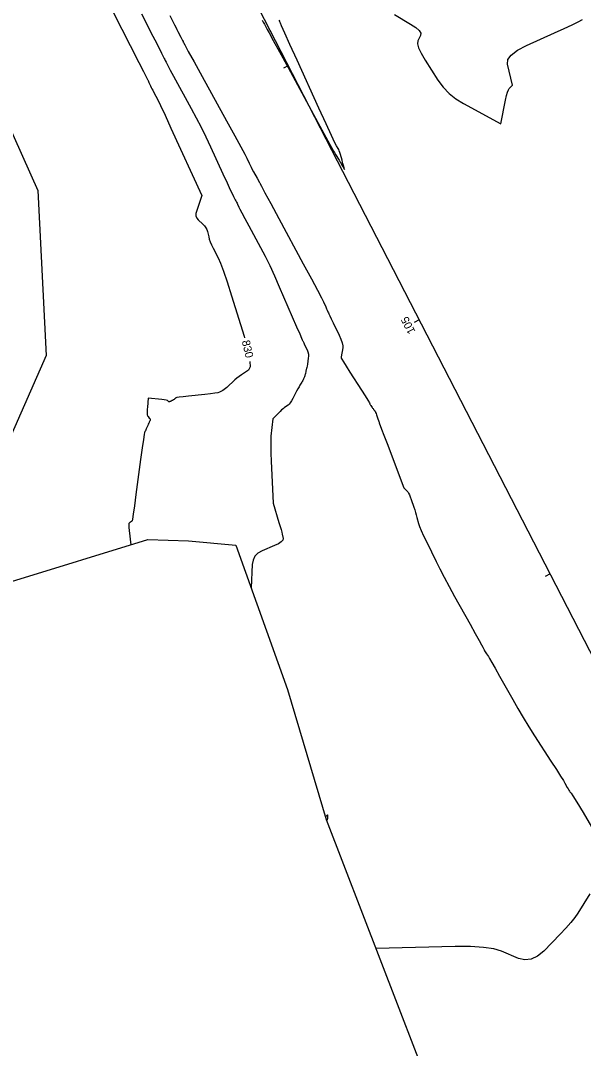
# Model space of a CAD drawing. Extents: x 1715724 to 1716561, y 394063 to 395906.
# Drawn here: x 1716070.7 to 1716169.2, y 394769.7 to 394949.5 of the extents above; entities that cross this region are included whole.
import ezdxf

# ---------------------------------------------------------------- set-up
doc = ezdxf.new("R2010")
doc.units = 0
for name, color, linetype in [('DT_X_Contour_Major', 7, 'Continuous'), ('DT_X_Contour_Minor', 7, 'Continuous'), ('DT_X_TIN_Hull', 7, 'Continuous'), ('GE_P_CL_10', 7, 'Continuous')]:
    doc.layers.add(name, color=color, linetype=linetype)

msp = doc.modelspace()

# ---------------------------------------------------------------- linework, layer by layer
at = {"layer": 'DT_X_Contour_Major'}
for points in [[(1716086.92, 394951.04), (1716091.41, 394942.22), (1716092.21, 394940.65), (1716092.69, 394939.69), (1716092.87, 394939.34), (1716092.92, 394939.24), (1716092.95, 394939.18), (1716093, 394939.07), (1716093.08, 394938.91), (1716093.17, 394938.71), (1716093.46, 394938.1), (1716093.57, 394937.86), (1716093.69, 394937.62), (1716093.83, 394937.36), (1716093.98, 394937.09), (1716094.39, 394936.34), (1716094.66, 394935.78), (1716095.19, 394934.66), (1716095.98, 394932.98), (1716097.01, 394930.73), (1716102.41, 394918.93), (1716101.52, 394916.34), (1716101.39, 394915.82), (1716101.39, 394915.37), (1716101.51, 394914.98), (1716101.76, 394914.66), (1716102.6, 394913.91), (1716102.88, 394913.61), (1716103.11, 394913.3), (1716103.28, 394912.98), (1716103.39, 394912.64), (1716103.61, 394911.7), (1716103.72, 394911.31), (1716103.89, 394910.85), (1716104.12, 394910.32), (1716104.42, 394909.72), (1716105.28, 394908.02), (1716105.67, 394907.13), (1716106.18, 394905.73), (1716106.82, 394903.83), (1716107.59, 394901.42), (1716109.8, 394894.32), (1716109.89, 394894.02)], [(1716110.82, 394889.93), (1716110.85, 394888.99), (1716110.56, 394888.4), (1716109.35, 394887.59), (1716108.92, 394887.29), (1716108.53, 394887), (1716108.18, 394886.7), (1716107.87, 394886.42), (1716107.09, 394885.65), (1716106.81, 394885.38), (1716106.54, 394885.16), (1716106.3, 394884.98), (1716106.08, 394884.85), (1716105.53, 394884.56), (1716105.21, 394884.45), (1716104.68, 394884.34), (1716103.92, 394884.23), (1716102.96, 394884.12), (1716100.09, 394883.83), (1716099.15, 394883.73), (1716098.47, 394883.66), (1716098.05, 394883.6), (1716097.9, 394883.57), (1716097.85, 394883.52), (1716097.84, 394883.5), (1716097.81, 394883.48), (1716097.79, 394883.46), (1716097.77, 394883.44), (1716097.7, 394883.38), (1716097.67, 394883.35), (1716097.64, 394883.33), (1716097.6, 394883.3), (1716097.57, 394883.28), (1716097.46, 394883.2), (1716097.41, 394883.18), (1716097.36, 394883.14), (1716097.29, 394883.11), (1716097.22, 394883.07), (1716097.02, 394882.97), (1716096.95, 394882.93), (1716096.89, 394882.9), (1716096.84, 394882.88), (1716096.8, 394882.86), (1716096.72, 394882.83), (1716096.69, 394882.82), (1716096.66, 394882.83), (1716096.62, 394882.86), (1716096.58, 394882.9), (1716096.48, 394883.02), (1716096.38, 394883.07), (1716096.17, 394883.12), (1716095.84, 394883.18), (1716095.39, 394883.23), (1716093.02, 394883.51), (1716092.89, 394881.89), (1716092.86, 394881.57), (1716092.85, 394881.31), (1716092.84, 394881.12), (1716092.83, 394880.98), (1716092.83, 394880.7), (1716092.85, 394880.59), (1716092.88, 394880.48), (1716092.93, 394880.38), (1716093, 394880.28), (1716093.22, 394880.01), (1716093.3, 394879.91), (1716093.35, 394879.84), (1716093.38, 394879.79), (1716093.38, 394879.75), (1716093.37, 394879.69), (1716093.37, 394879.65), (1716093.35, 394879.61), (1716093.33, 394879.56), (1716093.31, 394879.5), (1716093.22, 394879.31), (1716093.18, 394879.23), (1716093.13, 394879.1), (1716093.05, 394878.93), (1716092.96, 394878.73), (1716092.69, 394878.13), (1716092.6, 394877.93), (1716092.53, 394877.77), (1716092.47, 394877.66), (1716092.44, 394877.59), (1716092.37, 394877.47), (1716092.31, 394877.14), (1716092.18, 394876.25), (1716091.98, 394874.79), (1716091.71, 394872.78), (1716090.89, 394866.65), (1716090.62, 394864.64), (1716090.41, 394863.19), (1716090.28, 394862.32), (1716090.22, 394862.01), (1716090.14, 394861.95), (1716090.11, 394861.93), (1716090.09, 394861.92), (1716090.08, 394861.91), (1716090.08, 394861.9), (1716090.07, 394861.9), (1716090.06, 394861.9), (1716090.05, 394861.89), (1716090.03, 394861.87), (1716090, 394861.86), (1716089.92, 394861.8), (1716089.89, 394861.78), (1716089.86, 394861.75), (1716089.82, 394861.71), (1716089.78, 394861.66), (1716089.67, 394861.54), (1716089.64, 394861.43), (1716089.64, 394861.2), (1716089.66, 394860.84), (1716089.71, 394860.36), (1716089.99, 394857.84)]]:
    msp.add_lwpolyline(points, dxfattribs=at)
at = {"layer": 'DT_X_Contour_Minor'}
for points in [[(1716091.87, 394950.73), (1716093.86, 394946.82), (1716094.52, 394945.51), (1716095.37, 394943.84), (1716095.56, 394943.48), (1716095.83, 394942.93), (1716095.93, 394942.73), (1716096.02, 394942.55), (1716096.17, 394942.25), (1716096.34, 394941.89), (1716096.5, 394941.57), (1716096.87, 394940.89), (1716097.44, 394939.84), (1716100.57, 394934.17), (1716101.44, 394932.55), (1716102.29, 394930.89), (1716103.13, 394929.18), (1716103.95, 394927.43), (1716106.11, 394922.71), (1716106.84, 394921.13), (1716107.39, 394919.94), (1716107.76, 394919.15), (1716107.97, 394918.75), (1716108.27, 394918.2), (1716108.38, 394918), (1716108.49, 394917.8), (1716108.58, 394917.6), (1716108.67, 394917.41), (1716108.89, 394916.9), (1716109.07, 394916.55), (1716109.41, 394915.9), (1716109.93, 394914.93), (1716110.62, 394913.65), (1716112.69, 394909.82), (1716113.47, 394908.32), (1716114.28, 394906.68), (1716115.1, 394904.9), (1716115.95, 394902.99), (1716118.24, 394897.71), (1716118.99, 394895.98), (1716119.53, 394894.73), (1716119.86, 394893.97), (1716119.99, 394893.69), (1716120.03, 394893.6), (1716120.07, 394893.53), (1716120.14, 394893.38), (1716120.25, 394893.15), (1716120.4, 394892.84), (1716120.84, 394891.92), (1716120.97, 394891.57), (1716121.05, 394891.21), (1716121.07, 394890.84), (1716121.04, 394890.46), (1716120.87, 394889.44), (1716120.82, 394889.1), (1716120.77, 394888.85), (1716120.74, 394888.68), (1716120.72, 394888.61), (1716120.68, 394888.51), (1716120.66, 394888.46), (1716120.64, 394888.39), (1716120.62, 394888.29), (1716120.59, 394888.16), (1716120.52, 394887.79), (1716120.49, 394887.65), (1716120.45, 394887.51), (1716120.41, 394887.37), (1716120.35, 394887.23), (1716120.2, 394886.85), (1716120.14, 394886.71), (1716120.07, 394886.57), (1716119.99, 394886.43), (1716119.91, 394886.3), (1716119.67, 394885.94), (1716119.57, 394885.76), (1716119.42, 394885.5), (1716119.23, 394885.15), (1716119, 394884.72), (1716118.35, 394883.45), (1716118.11, 394883.02), (1716117.89, 394882.68), (1716117.68, 394882.43), (1716117.5, 394882.27), (1716117.02, 394881.95), (1716116.83, 394881.81), (1716116.62, 394881.63), (1716116.37, 394881.42), (1716116.11, 394881.16), (1716114.81, 394879.88), (1716114.51, 394876.87), (1716114.47, 394876.11), (1716114.46, 394875.12), (1716114.48, 394873.89), (1716114.54, 394872.44), (1716114.89, 394865.12), (1716115.91, 394861.72), (1716116.11, 394861.05), (1716116.27, 394860.49), (1716116.39, 394860.04), (1716116.47, 394859.7), (1716116.63, 394858.94), (1716116.58, 394858.64), (1716116.31, 394858.34), (1716115.82, 394858.02), (1716115.12, 394857.69), (1716112.95, 394856.78), (1716112.23, 394856.38), (1716111.71, 394855.84), (1716111.38, 394855.17), (1716111.24, 394854.37), (1716111.03, 394850.32)], [(1716096.82, 394950.42), (1716097.42, 394949.24), (1716097.64, 394948.81), (1716097.85, 394948.39), (1716098.05, 394948), (1716098.24, 394947.62), (1716098.75, 394946.62), (1716098.92, 394946.29), (1716099.04, 394946.04), (1716099.12, 394945.88), (1716099.17, 394945.79), (1716099.22, 394945.68), (1716099.43, 394945.28), (1716100.05, 394944.16), (1716101.06, 394942.33), (1716102.47, 394939.77), (1716106.75, 394932), (1716108.17, 394929.41), (1716109.23, 394927.46), (1716109.93, 394926.15), (1716110.27, 394925.49), (1716110.68, 394924.59), (1716110.84, 394924.25), (1716111.03, 394923.88), (1716111.23, 394923.49), (1716111.46, 394923.08), (1716112.09, 394921.95), (1716112.3, 394921.58), (1716112.45, 394921.3), (1716112.55, 394921.13), (1716112.59, 394921.04), (1716112.63, 394920.96), (1716112.84, 394920.56), (1716113.45, 394919.42), (1716114.46, 394917.55), (1716115.87, 394914.94), (1716120.16, 394907.01), (1716121.58, 394904.37), (1716122.65, 394902.38), (1716123.34, 394901.05), (1716123.68, 394900.37), (1716124.08, 394899.45), (1716124.21, 394899.13), (1716124.32, 394898.89), (1716124.4, 394898.71), (1716124.46, 394898.61), (1716124.56, 394898.41), (1716124.64, 394898.24), (1716124.81, 394897.9), (1716125.06, 394897.37), (1716125.4, 394896.66), (1716126.41, 394894.53), (1716126.74, 394893.79), (1716126.96, 394893.16), (1716127.06, 394892.66), (1716127.06, 394892.27), (1716126.81, 394890.72), (1716126.8, 394890.51), (1716126.9, 394890.32), (1716127.18, 394889.85), (1716127.65, 394889.1), (1716128.31, 394888.06), (1716130.33, 394884.9), (1716130.99, 394883.87), (1716131.46, 394883.12), (1716131.74, 394882.66), (1716131.83, 394882.5), (1716131.81, 394882.45), (1716131.81, 394882.42), (1716131.84, 394882.36), (1716131.89, 394882.28), (1716131.97, 394882.18), (1716132.21, 394881.87), (1716132.29, 394881.76), (1716132.36, 394881.67), (1716132.42, 394881.59), (1716132.47, 394881.53), (1716132.57, 394881.38), (1716132.61, 394881.33), (1716132.64, 394881.29), (1716132.67, 394881.25), (1716132.69, 394881.22), (1716132.74, 394881.15), (1716132.77, 394881.09), (1716132.81, 394880.97), (1716132.88, 394880.8), (1716132.96, 394880.56), (1716133.21, 394879.85), (1716133.29, 394879.61), (1716133.36, 394879.42), (1716133.41, 394879.27), (1716133.45, 394879.18), (1716133.52, 394879), (1716133.62, 394878.73), (1716133.87, 394878.07), (1716134.27, 394877), (1716134.82, 394875.55), (1716137.72, 394867.82), (1716138.42, 394867.08), (1716138.57, 394866.87), (1716138.72, 394866.59), (1716138.88, 394866.22), (1716139.05, 394865.76), (1716139.5, 394864.44), (1716139.65, 394863.96), (1716139.8, 394863.49), (1716139.93, 394863.06), (1716140.04, 394862.64), (1716140.33, 394861.57), (1716140.5, 394861.06), (1716140.79, 394860.34), (1716141.21, 394859.41), (1716141.76, 394858.27), (1716143.38, 394854.93), (1716144.05, 394853.61), (1716144.81, 394852.15), (1716145.67, 394850.54), (1716146.64, 394848.79), (1716149.35, 394843.93), (1716150.25, 394842.31), (1716150.92, 394841.1), (1716151.35, 394840.31), (1716151.56, 394839.93), (1716151.79, 394839.46), (1716151.88, 394839.28), (1716151.98, 394839.11), (1716152.09, 394838.93), (1716152.21, 394838.75), (1716152.54, 394838.28), (1716152.76, 394837.94), (1716153.16, 394837.25), (1716153.74, 394836.23), (1716154.5, 394834.86), (1716156.79, 394830.76), (1716157.67, 394829.21), (1716158.6, 394827.63), (1716159.59, 394826.02), (1716160.63, 394824.39), (1716163.48, 394819.99), (1716164.44, 394818.51), (1716165.16, 394817.37), (1716165.66, 394816.58), (1716165.93, 394816.13), (1716166.34, 394815.39), (1716166.48, 394815.14), (1716166.61, 394814.93), (1716166.72, 394814.76), (1716166.81, 394814.64), (1716167.04, 394814.39), (1716167.32, 394813.95), (1716168.01, 394812.81), (1716169.1, 394810.99), (1716170.6, 394808.47)], [(1716112.97, 394949.64), (1716113.17, 394949.27), (1716113.35, 394948.94), (1716113.5, 394948.66), (1716113.87, 394947.99), (1716114.2, 394947.38), (1716114.91, 394946.07), (1716116.01, 394944.05), (1716117.49, 394941.32), (1716121.95, 394933.11), (1716123.42, 394930.42), (1716124.47, 394928.49), (1716125.1, 394927.33), (1716125.31, 394926.94), (1716125.33, 394926.91), (1716125.36, 394926.85), (1716125.45, 394926.7), (1716125.6, 394926.46), (1716125.8, 394926.12), (1716126.41, 394925.1), (1716126.61, 394924.77), (1716126.76, 394924.52), (1716126.85, 394924.36), (1716126.89, 394924.3), (1716126.92, 394924.25), (1716126.94, 394924.22), (1716126.97, 394924.16), (1716127.01, 394924.09), (1716127.07, 394924), (1716127.36, 394923.51), (1716127.23, 394924.06), (1716127.2, 394924.17), (1716127.18, 394924.24), (1716127.17, 394924.29), (1716127.16, 394924.31), (1716127.15, 394924.33), (1716127.13, 394924.39), (1716127.09, 394924.53), (1716127.03, 394924.77), (1716126.94, 394925.1), (1716126.67, 394926.1), (1716126.56, 394926.45), (1716126.46, 394926.74), (1716126.36, 394926.99), (1716126.25, 394927.18), (1716125.97, 394927.63), (1716125.7, 394928.17), (1716125.1, 394929.46), (1716124.16, 394931.48), (1716122.9, 394934.25), (1716119.08, 394942.61), (1716117.82, 394945.37), (1716116.92, 394947.37), (1716116.36, 394948.6), (1716116.16, 394949.07), (1716116.08, 394949.3), (1716116.03, 394949.43), (1716115.94, 394949.64)], [(1716136.14, 394950.59), (1716138.94, 394948.9), (1716139.84, 394948.31), (1716140.43, 394947.78), (1716140.7, 394947.32), (1716140.67, 394946.93), (1716140.17, 394945.98), (1716140.12, 394945.5), (1716140.31, 394944.79), (1716140.76, 394943.83), (1716141.47, 394942.64), (1716143.7, 394939.14), (1716144.6, 394937.89), (1716145.65, 394936.79), (1716146.84, 394935.83), (1716148.17, 394935.01), (1716154.7, 394931.49), (1716155.55, 394935.63), (1716155.73, 394936.42), (1716155.89, 394937.02), (1716156.04, 394937.43), (1716156.17, 394937.64), (1716156.77, 394938.22), (1716155.91, 394941.92), (1716155.97, 394942.72), (1716156.55, 394943.52), (1716157.63, 394944.34), (1716159.21, 394945.16), (1716164.12, 394947.38), (1716165.8, 394948.14), (1716167.18, 394948.79), (1716168.26, 394949.32), (1716169.03, 394949.72)], [(1716124.21, 394809.72), (1716124.3, 394809.72), (1716124.32, 394809.72), (1716124.34, 394809.73), (1716124.36, 394809.74), (1716124.37, 394809.76), (1716124.4, 394809.8), (1716124.42, 394809.84), (1716124.42, 394809.89), (1716124.43, 394809.98), (1716124.43, 394810.09), (1716124.44, 394810.42), (1716124.43, 394810.52), (1716124.41, 394810.57), (1716124.37, 394810.58), (1716124.32, 394810.54), (1716124.05, 394810.24)], [(1716170.27, 394796.79), (1716168.18, 394793.38), (1716167.65, 394792.61), (1716166.96, 394791.74), (1716166.11, 394790.77), (1716165.11, 394789.71), (1716162.21, 394786.77), (1716161.12, 394785.86), (1716160.03, 394785.34), (1716158.92, 394785.22), (1716157.82, 394785.49), (1716154.85, 394786.74), (1716153.51, 394787.14), (1716151.7, 394787.41), (1716149.43, 394787.54), (1716146.7, 394787.54), (1716132.86, 394787.23)]]:
    msp.add_lwpolyline(points, dxfattribs=at)
at = {"layer": 'DT_X_TIN_Hull'}
for points in [[(1716061.25, 394947.63), (1716073.72, 394919.83), (1716075.2, 394890.97), (1716064.15, 394865.97)], [(1716069.1, 394851.42), (1716092.99, 394858.76), (1716100.06, 394858.56), (1716108.35, 394857.76), (1716117.42, 394832.55), (1716124.19, 394809.79), (1716142.92, 394761.05)]]:
    msp.add_lwpolyline(points, dxfattribs=at)
at = {"layer": 'GE_P_CL_10'}
for p, q in [((1716249.46, 394685.42), (1715852.54, 395456.56)), ((1716117.57, 394941.66), (1716116.68, 394941.2)), ((1716140.45, 394897.2), (1716139.56, 394896.74)), ((1716163.33, 394852.75), (1716162.45, 394852.29))]:
    msp.add_line(p, q, dxfattribs=at)

# ---------------------------------------------------------------- texts
at = {"layer": 'DT_X_Contour_Major'}
msp.add_text('830', height=1.4, rotation=282.9201, dxfattribs=at).set_placement((1716109.4, 394893.46))
at = {"layer": 'GE_P_CL_10'}
msp.add_text('105', height=1.4, rotation=117.2357, dxfattribs=at).set_placement((1716139.82, 394895.15))

doc.saveas('drawing.dxf')
